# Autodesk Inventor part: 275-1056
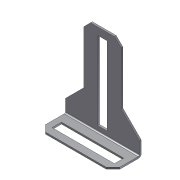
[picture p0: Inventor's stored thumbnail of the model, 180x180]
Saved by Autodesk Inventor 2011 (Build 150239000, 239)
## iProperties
Company: Autodesk Inc.
Created: 2005-07
Part Number: 275-1056
Document SubType Name: Sheet Metal
Designer: Autodesk Inc.
Density: 1 g/cm^3
Sheet Metal Rule: Default
Catalog Web Link: http://www.vexrobotics.com/products/accessories/structure/angle-gusset.html
Description: Bent gusset for strengthening "T" joints. Slots on both main flanges allow for adjustment on two axis.
Vendor: Innovation First, Inc.
Title: VEX Robotics Kit of Parts
Author: Autodesk Inc.
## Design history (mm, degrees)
node "Face2"
  sketch "Sketch1"
    geometry: L1 (-11.423, 23.011)-(0.007, 23.011); L2 (3.182, 19.836)-(3.182, -5.564); L3 (3.182, -21.439)-(-14.598, -21.439); L4 (-14.598, -5.564)-(-14.598, 19.836); L5 (-11.423, 23.011)-(-14.598, 19.836); L6 (3.182, 19.836)-(0.007, 23.011); L7 (-14.598, -21.439)-(-23.488, -21.439); L8 (-23.488, -21.439)-(-23.488, -14.454); L9 (-23.488, -14.454)-(-14.598, -5.564); L10 (3.182, -21.439)-(12.072, -21.439); L11 (12.072, -21.439)-(12.072, -14.454); L12 (12.072, -14.454)-(3.182, -5.564); L13 (-7.994, 19.455)-(-3.422, 19.455); L14 (-3.422, 19.455)-(-3.422, -18.01); L15 (-3.422, -18.01)-(-7.994, -18.01); L16 (-7.994, -18.01)-(-7.994, 19.455); 2 further points
    constraints: 32 end point, 8 perpendicular, 4 parallel, 4 point on line, 2 horizontal
    dimensions: "d0" = 44.45 distance between parallel lines of L3 L1; "d1" = 3.175 distance of L1.start point (-14.598, 23.011); "d2" = 3.175 distance of L4.end point (-14.598, 23.011) (= d1); "d3" = 3.175 distance of L2.start point (3.182, 23.011) (= d1); "d4" = 3.175 distance of L1.end point (3.182, 23.011) (= d3); "d6" = 35.56 distance between parallel lines of L11 L8; "d7" = 17.78 distance between parallel lines of L2 L4; "d8" = 8.89 horizontal distance of L11.end L2.end; "d9" = 6.985 distance of L7.end L8.end; "d10" = 6.985 distance of L10.end L11.end; "d11" = 3.556 distance between parallel lines of L1 L13; "d12" = 4.572 distance of L13.start L13.end; "d13" = 6.604 distance between parallel lines of L4 L16; "d14" = 3.429 distance between parallel lines of L3 L15
node "Flange1"
chamfer "Chamfer1" distance "d24" = 3.175; stored, may be unused: second distance "d25" = 3.175, angle "d26" = 45 deg
sketch "Sketch3"
  geometry: L1 (35.56, 0)-(35.56, -8.89) reference; L2 (0, -8.89)-(0, 0) reference; L3 (32.385, -12.065)-(3.175, -12.065) reference; L4 (2.794, -4.064)-(32.766, -4.064); L5 (32.766, -4.064)-(32.766, -8.636); L6 (32.766, -8.636)-(2.794, -8.636); L7 (2.794, -8.636)-(2.794, -4.064)
  constraints: 8 end point, 2 parallel, 1 horizontal, 1 perpendicular
  dimensions: "d27" = 2.794 distance between parallel lines of L2 L7; "d28" = 2.794 distance between parallel lines of L1 L5; "d29" = 3.429 distance between parallel lines of L3 L6; "d30" = 4.572 distance between parallel lines of L6 L4
extrude "Extrusion1" cut sketch "Sketch3" distance "d31" = 25.4; taper "d32" = 0 deg
body "Solid1"
face "Plate2" dims "Thickness" = 0.8509
sketch "Sketch2"
  geometry: L1 (35.56, 0)-(35.56, 12.7); L2 (35.56, 12.7)-(0, 12.7); 2 other entities
  constraints: 4 end point, 4 other
face "Plate3" dims "d17" = 0.8509 (= BendReliefWidth), "d19" = 1.7018 (= MinimumRemnant), "d21" = 12.7, "d22" = 90 deg, "d23" = 0.635, "Thickness" = 0.8509
bend "Bend1" dims "d17" = 0.8509 (= BendReliefWidth), "d18" = 0.42545 (= BendReliefDepth), "d19" = 1.7018 (= MinimumRemnant), "d20" = 0.8509 (= BendRadius), "d21" = 12.7, "d22" = 90 deg, "d23" = 0.635, "SeamGap" = 0.00508, "Thickness" = 0.8509
other parameters: "BendRadius" = 0.8509 (= Thickness), "BendReliefWidth" = 0.8509 (= Thickness), "BendReliefDepth" = 0.42545 (= 0.5 x Thickness), "CornerReliefSize" = 3.4036 (= 4 x Thickness), "MinimumRemnant" = 1.7018 (= 2 x Thickness), "TransitionRadius" = 0.8509 (= BendRadius), "d15" = 0.8509 (= BendRadius), "d16" = 0.8509 (= BendRadius), "JacobiRadiusSize" = 0.8509 (= Thickness), "GapSize" = 0.8509 (= Thickness)
